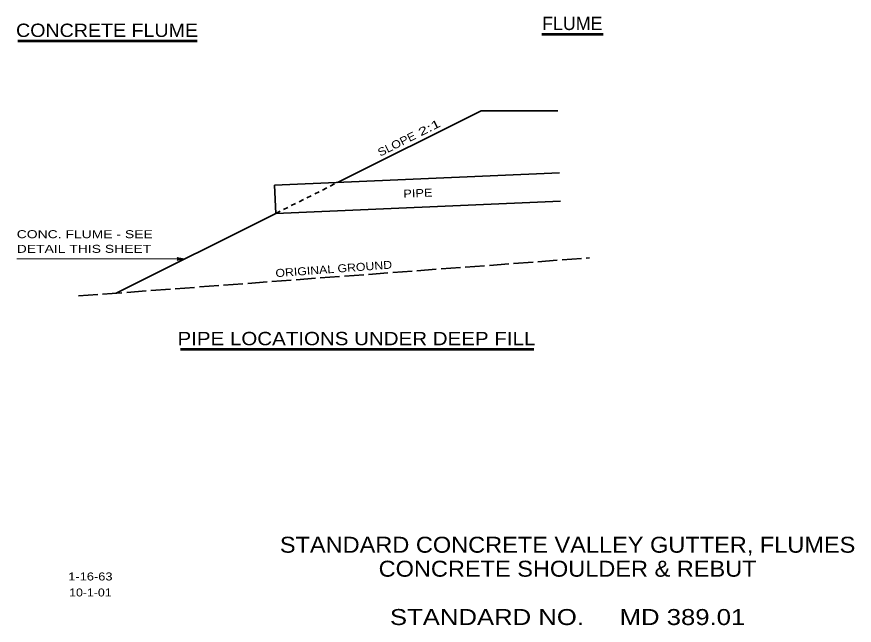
# Model space of a CAD drawing. Extents: x -10 to 104, y -162 to -1.
# Drawn here: x 0.5 to 104.2, y -162.2 to -86.9 of the extents above; entities that cross this region are included whole.
import ezdxf
from ezdxf.enums import TextEntityAlignment as Align

# ---------------------------------------------------------------- set-up
doc = ezdxf.new("R2010")
doc.units = 0
doc.header["$LTSCALE"] = 0.4
doc.linetypes.add('LONG_DASHED', pattern=[7.5, 6, -1.5])
doc.linetypes.add('SHORT_DASHED', pattern=[2.7, 1.5, -1.2])
for name, color, linetype, lineweight in [('1', 7, 'Continuous', 35), ('10', 7, 'Continuous', 13), ('12', 7, 'Continuous', 53)]:
    doc.layers.add(name, color=color, linetype=linetype, lineweight=lineweight)
doc.layers.add('13', color=7, linetype='Continuous')

msp = doc.modelspace()

# ---------------------------------------------------------------- linework, layer by layer
at = {"layer": '1'}
for p, q in [((57.9953, -98.5346), (40.2483, -107.4081)), ((57.9953, -98.5346), (67.4953, -98.5346)), ((32.4274, -107.7462), (67.6806, -106.2221)), ((32.4274, -107.7462), (32.5786, -111.243)), ((32.5786, -111.243), (67.8318, -109.7188)), ((32.5786, -111.243), (12.8267, -121.1189))]:
    msp.add_line(p, q, dxfattribs=at)
at = {"layer": '1', "linetype": 'SHORT_DASHED'}
msp.add_line((32.5786, -111.243), (40.2483, -107.4081), dxfattribs=at)
at = {"layer": '1', "linetype": 'LONG_DASHED'}
msp.add_line((8.1767, -121.466), (71.4244, -116.7453), dxfattribs=at)
at = {"layer": '10'}
msp.add_line((0.5408, -116.8767), (21.3112, -116.8767), dxfattribs=at)
msp.add_lwpolyline([(21.3112, -116.8767), (20.3791, -117.0514), (20.4509, -117.0017), (20.4879, -116.9392), (20.4987, -116.8767), (20.4879, -116.8142), (20.4509, -116.7517), (20.3791, -116.7019), (21.3112, -116.8767), (20.4509, -116.7517), (20.4879, -116.8142), (21.3112, -116.8767), (20.4987, -116.8767), (20.4879, -116.9392), (21.3112, -116.8767), (20.4509, -117.0017)], dxfattribs=at)
at = {"layer": '12'}
for p, q in [((65.5318, -89.0347), (73.1048, -89.0347)), ((0.6817, -89.8892), (22.8691, -89.8892)), ((20.7838, -128.0609), (64.5158, -128.0609))]:
    msp.add_line(p, q, dxfattribs=at)

# ---------------------------------------------------------------- texts
msp.add_text('FLUME', height=1.65, dxfattribs=at).set_placement((69.2859, -88.5347), align=Align.CENTER)
for s, width, p in [('CONCRETE FLUME', 1.1, (11.7124, -89.3892)), ('PIPE LOCATIONS UNDER DEEP FILL', 1.15, (42.5697, -127.5609))]:
    msp.add_text(s, height=1.65, dxfattribs=dict(at, width=width)).set_placement(p, align=Align.CENTER)
for s, rotation, width, p in [('SLOPE', 26.565, 1.15, (47.7779, -103.0843)), ('PIPE', 2.476, 1.2, (50.1991, -109.225)), ('ORIGINAL GROUND', 4.269, 1.15, (39.8002, -118.6043))]:
    msp.add_text(s, height=0.99, rotation=rotation, dxfattribs=dict(at, width=width)).set_placement(p, align=Align.CENTER)
at = {"layer": '12', "width": 1.3}
for s, p in [('CONC. FLUME - SEE', (0.5408, -114.3067)), ('DETAIL THIS SHEET', (0.5408, -116.1217))]:
    msp.add_text(s, height=0.99, dxfattribs=at).set_placement(p)
at = {"layer": '13', "width": 1.55}
msp.add_text('2:1', height=0.99, rotation=26.565, dxfattribs=at).set_placement((51.8029, -101.0718), align=Align.CENTER)
at = {"layer": '13'}
for s, height, width, p in [('STANDARD CONCRETE VALLEY GUTTER, FLUMES', 1.98, 1.1, (68.7002, -153.2582)), ('CONCRETE SHOULDER & REBUT', 1.98, 1.1, (68.7002, -156.2282)), ('1-16-63', 0.99, 1.2, (9.6524, -156.6942)), ('10-1-01', 0.99, 1.15, (9.6524, -158.6742)), ('STANDARD NO.     MD 389.01', 1.98, 1.2, (68.7002, -162.2128))]:
    msp.add_text(s, height=height, dxfattribs=dict(at, width=width)).set_placement(p, align=Align.CENTER)

doc.saveas('drawing.dxf')
